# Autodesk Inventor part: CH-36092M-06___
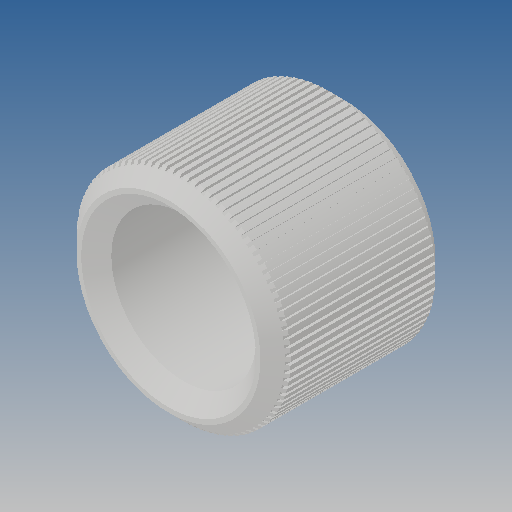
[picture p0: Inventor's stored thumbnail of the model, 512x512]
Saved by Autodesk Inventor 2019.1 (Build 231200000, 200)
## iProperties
Created: 2012-09
Part Number: CH-36092M-06___
Material: Ogólny
Document SubType Name: Modeling
Designer: CADENGINEERING4
Density: 1 g/cm^3
Appearance: Domyślna
Author: CADENGINEERING4
Revision Number: ÈÎºÎ
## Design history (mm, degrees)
feature "NONE"
node "Bryła1"
